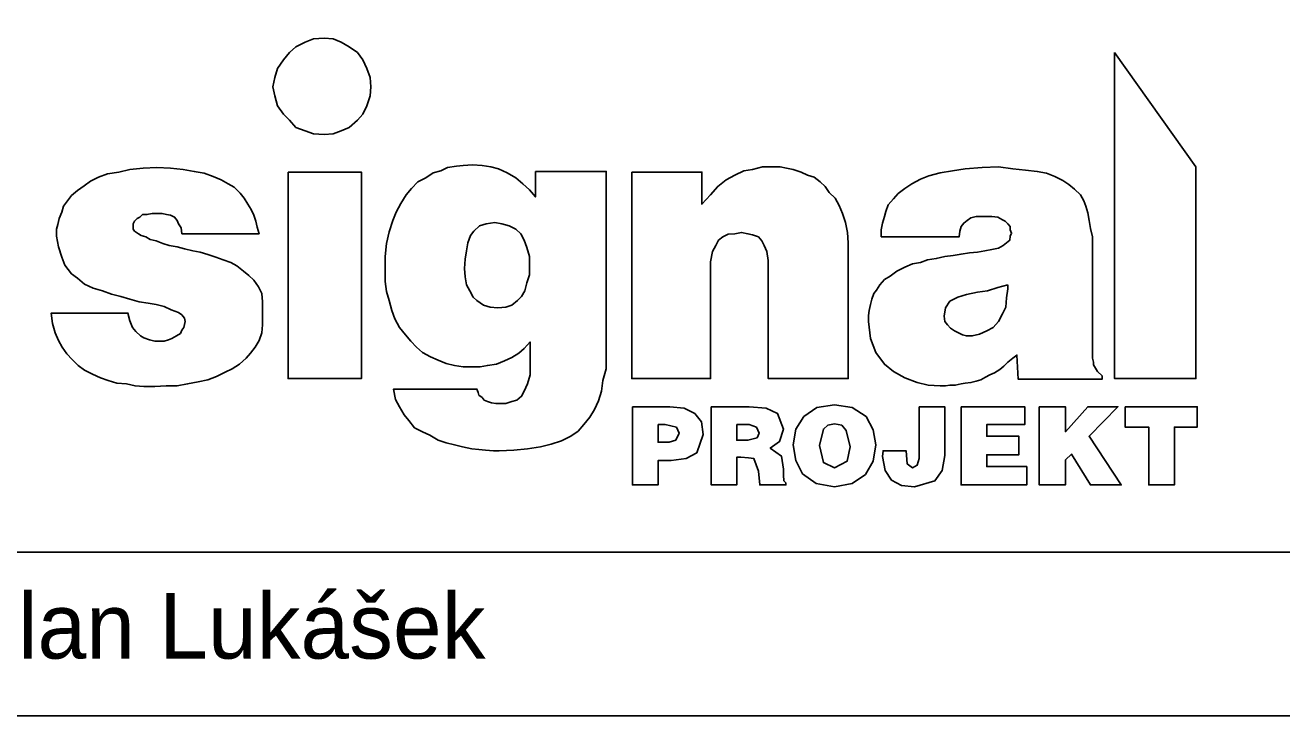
# Model space of a CAD drawing. Extents: x -1210 to -790, y -790 to -493.
# Drawn here: x -866.75 to -828.37, y -690 to -668.9 of the extents above; entities that cross this region are included whole.
import ezdxf

# ---------------------------------------------------------------- set-up
doc = ezdxf.new("R2010")
doc.units = 0
for name, color, linetype in [('Info o rozpiskách', 7, 'Continuous'), ('popis', 7, 'Continuous'), ('Rozpiska_pole_6', 7, 'Continuous')]:
    doc.layers.add(name, color=color, linetype=linetype)

msp = doc.modelspace()

# ---------------------------------------------------------------- linework, layer by layer
at = {"layer": 'Info o rozpiskách'}
for points in [[(-857.618, -669.303), (-857.338, -669.322), (-857.097, -669.422), (-856.857, -669.563), (-856.597, -669.743), (-856.437, -669.963), (-856.316, -670.224), (-856.216, -670.504), (-856.196, -670.785), (-856.216, -671.065), (-856.316, -671.366), (-856.437, -671.626), (-856.597, -671.806), (-856.857, -672.027), (-857.097, -672.127), (-857.338, -672.227), (-857.618, -672.247), (-857.939, -672.227), (-858.199, -672.127), (-858.48, -672.027), (-858.68, -671.806), (-858.86, -671.626), (-859.041, -671.366), (-859.121, -671.065), (-859.181, -670.785), (-859.121, -670.504), (-859.041, -670.224), (-858.86, -669.963), (-858.68, -669.743), (-858.48, -669.563), (-858.199, -669.422), (-857.939, -669.322), (-857.618, -669.303)], [(-848.203, -680.56), (-847.061, -680.56), (-846.621, -680.601), (-846.3, -680.761), (-846.1, -681.022), (-846.04, -681.402), (-846.24, -681.963), (-846.561, -682.144), (-847.021, -682.203), (-847.422, -682.203), (-847.422, -682.945), (-848.203, -682.945), (-848.203, -680.56)], [(-845.799, -680.56), (-844.637, -680.56), (-844.117, -680.601), (-843.776, -680.761), (-843.596, -681.242), (-843.716, -681.622), (-843.996, -681.823), (-843.656, -682.063), (-843.596, -682.464), (-843.596, -682.644), (-843.576, -682.825), (-843.515, -682.885), (-843.515, -682.945), (-844.317, -682.945), (-844.357, -682.524), (-844.497, -682.144), (-844.658, -682.123), (-844.898, -682.103), (-845.018, -682.103), (-845.018, -682.945), (-845.799, -682.945), (-845.799, -680.56)], [(-842.033, -680.501), (-841.492, -680.581), (-841.071, -680.861), (-840.851, -681.262), (-840.771, -681.722), (-840.851, -682.223), (-841.092, -682.624), (-841.492, -682.904), (-842.033, -683.004), (-842.594, -682.904), (-843.015, -682.604), (-843.215, -682.203), (-843.295, -681.722), (-843.215, -681.242), (-842.975, -680.861), (-842.574, -680.581), (-842.033, -680.501)], [(-839.45, -680.56), (-838.668, -680.56), (-838.668, -682.043), (-838.749, -682.504), (-838.969, -682.825), (-839.59, -683.004), (-839.991, -682.964), (-840.291, -682.804), (-840.491, -682.504), (-840.572, -682.083), (-840.552, -681.903), (-839.85, -681.903), (-839.81, -682.304), (-839.65, -682.423), (-839.51, -682.344), (-839.45, -682.144), (-839.45, -680.56)], [(-838.168, -680.56), (-836.224, -680.56), (-836.224, -681.101), (-837.387, -681.101), (-837.387, -681.462), (-836.405, -681.462), (-836.405, -682.023), (-837.387, -682.023), (-837.387, -682.384), (-836.165, -682.384), (-836.165, -682.945), (-838.168, -682.945), (-838.168, -680.56)], [(-835.784, -680.56), (-834.983, -680.56), (-834.983, -681.322), (-834.302, -680.56), (-833.38, -680.56), (-834.261, -681.462), (-833.28, -682.945), (-834.221, -682.945), (-834.802, -682.003), (-834.983, -682.183), (-834.983, -682.945), (-835.784, -682.945), (-835.784, -680.56)], [(-833.159, -680.56), (-830.956, -680.56), (-830.956, -681.182), (-831.657, -681.182), (-831.657, -682.945), (-832.439, -682.945), (-832.439, -681.182), (-833.159, -681.182), (-833.159, -680.56)], [(-847.422, -681.101), (-847.422, -681.642), (-847.081, -681.642), (-846.881, -681.582), (-846.781, -681.362), (-846.861, -681.182), (-847.202, -681.101), (-847.422, -681.101)], [(-845.018, -681.101), (-845.018, -681.582), (-844.677, -681.582), (-844.397, -681.503), (-844.337, -681.362), (-844.417, -681.182), (-844.637, -681.101), (-845.018, -681.101)], [(-842.033, -681.082), (-842.233, -681.122), (-842.374, -681.242), (-842.494, -681.742), (-842.374, -682.263), (-842.033, -682.423), (-841.652, -682.223), (-841.552, -681.782), (-841.673, -681.282), (-841.812, -681.122), (-842.033, -681.082)]]:
    msp.add_lwpolyline(points, dxfattribs=at)
at = {"layer": 'popis'}
for points in [[(-833.48, -669.743), (-833.48, -679.7), (-830.996, -679.7), (-830.996, -673.229), (-833.48, -669.743)], [(-861.966, -675.272), (-859.602, -675.272), (-859.662, -675.072), (-859.702, -674.891), (-859.762, -674.712), (-859.842, -674.531), (-859.943, -674.371), (-860.062, -674.19), (-860.182, -674.03), (-860.363, -673.85), (-860.543, -673.75), (-860.763, -673.629), (-861.004, -673.529), (-861.284, -673.429), (-861.585, -673.369), (-861.925, -673.309), (-862.306, -673.269), (-862.726, -673.249), (-863.147, -673.269), (-863.548, -673.309), (-863.888, -673.389), (-864.229, -673.449), (-864.51, -673.549), (-864.75, -673.669), (-864.95, -673.81), (-865.151, -673.95), (-865.331, -674.11), (-865.451, -674.271), (-865.572, -674.431), (-865.631, -674.611), (-865.712, -674.812), (-865.751, -674.991), (-865.792, -675.132), (-865.792, -675.353), (-865.732, -675.673), (-865.631, -675.993), (-865.531, -676.234), (-865.331, -676.494), (-865.151, -676.634), (-864.931, -676.815), (-864.67, -676.935), (-864.39, -677.015), (-864.109, -677.115), (-863.828, -677.195), (-863.548, -677.275), (-863.268, -677.356), (-862.987, -677.395), (-862.747, -677.435), (-862.506, -677.496), (-862.286, -677.596), (-862.066, -677.676), (-861.966, -677.756), (-861.885, -677.856), (-861.865, -677.956), (-861.906, -678.137), (-861.966, -678.217), (-862.006, -678.317), (-862.126, -678.397), (-862.266, -678.478), (-862.366, -678.517), (-862.506, -678.557), (-862.647, -678.557), (-862.787, -678.557), (-862.947, -678.517), (-863.128, -678.457), (-863.228, -678.397), (-863.368, -678.257), (-863.468, -678.137), (-863.548, -677.937), (-863.608, -677.696), (-865.952, -677.696), (-865.912, -678.016), (-865.832, -678.297), (-865.732, -678.538), (-865.612, -678.738), (-865.471, -678.938), (-865.311, -679.119), (-865.131, -679.298), (-864.931, -679.439), (-864.69, -679.559), (-864.45, -679.679), (-864.209, -679.759), (-863.949, -679.839), (-863.648, -679.86), (-863.388, -679.92), (-863.128, -679.94), (-862.787, -679.94), (-862.446, -679.92), (-862.106, -679.92), (-861.785, -679.86), (-861.465, -679.8), (-861.165, -679.739), (-860.904, -679.639), (-860.643, -679.499), (-860.423, -679.398), (-860.203, -679.259), (-860.002, -679.078), (-859.862, -678.918), (-859.722, -678.738), (-859.602, -678.538), (-859.522, -678.297), (-859.501, -678.057), (-859.501, -677.816), (-859.501, -677.756), (-859.501, -677.696), (-859.501, -677.636), (-859.501, -677.576), (-859.501, -677.496), (-859.501, -677.435), (-859.501, -677.395), (-859.501, -677.356), (-859.522, -677.095), (-859.622, -676.895), (-859.762, -676.694), (-859.922, -676.554), (-860.082, -676.414), (-860.282, -676.254), (-860.463, -676.153), (-860.703, -676.073), (-860.924, -675.993), (-861.165, -675.913), (-861.404, -675.833), (-861.625, -675.793), (-861.885, -675.733), (-862.106, -675.673), (-862.346, -675.632), (-862.547, -675.572), (-862.747, -675.493), (-862.927, -675.453), (-863.067, -675.372), (-863.207, -675.332), (-863.288, -675.272), (-863.407, -675.192), (-863.448, -675.132), (-863.448, -675.052), (-863.448, -674.972), (-863.407, -674.891), (-863.328, -674.812), (-863.247, -674.771), (-863.168, -674.691), (-863.027, -674.691), (-862.867, -674.651), (-862.726, -674.651), (-862.566, -674.651), (-862.426, -674.691), (-862.306, -674.712), (-862.186, -674.771), (-862.106, -674.872), (-862.066, -674.972), (-861.985, -675.092), (-861.966, -675.272)], [(-858.72, -673.389), (-858.72, -679.7), (-856.477, -679.7), (-856.477, -673.389), (-858.72, -673.389)], [(-851.168, -673.369), (-851.168, -674.15), (-851.349, -673.93), (-851.549, -673.75), (-851.769, -673.569), (-852.03, -673.409), (-852.29, -673.289), (-852.53, -673.229), (-852.791, -673.188), (-853.091, -673.169), (-853.372, -673.188), (-853.572, -673.209), (-853.852, -673.249), (-854.053, -673.349), (-854.293, -673.409), (-854.513, -673.569), (-854.754, -673.69), (-854.954, -673.89), (-855.115, -674.09), (-855.275, -674.35), (-855.415, -674.611), (-855.515, -674.872), (-855.635, -675.212), (-855.715, -675.572), (-855.756, -675.973), (-855.756, -676.394), (-855.756, -676.735), (-855.715, -677.035), (-855.635, -677.316), (-855.555, -677.616), (-855.455, -677.876), (-855.315, -678.137), (-855.134, -678.357), (-854.974, -678.557), (-854.794, -678.738), (-854.613, -678.898), (-854.374, -679.038), (-854.133, -679.138), (-853.893, -679.238), (-853.632, -679.298), (-853.372, -679.339), (-853.091, -679.339), (-852.85, -679.339), (-852.63, -679.298), (-852.35, -679.259), (-852.109, -679.159), (-851.889, -679.059), (-851.669, -678.918), (-851.509, -678.778), (-851.328, -678.578), (-851.328, -679.159), (-851.328, -679.579), (-851.409, -679.86), (-851.509, -680.08), (-851.589, -680.24), (-851.729, -680.36), (-851.889, -680.4), (-852.069, -680.46), (-852.269, -680.46), (-852.37, -680.46), (-852.51, -680.441), (-852.63, -680.4), (-852.731, -680.36), (-852.791, -680.281), (-852.891, -680.2), (-852.911, -680.12), (-852.951, -680.02), (-855.495, -680.02), (-855.435, -680.341), (-855.315, -680.56), (-855.175, -680.801), (-855.034, -680.981), (-854.854, -681.201), (-854.613, -681.322), (-854.393, -681.422), (-854.133, -681.582), (-853.893, -681.663), (-853.632, -681.722), (-853.391, -681.782), (-853.111, -681.842), (-852.891, -681.863), (-852.69, -681.883), (-852.45, -681.903), (-852.269, -681.903), (-851.829, -681.883), (-851.409, -681.842), (-851.008, -681.782), (-850.687, -681.703), (-850.367, -681.603), (-850.086, -681.462), (-849.866, -681.302), (-849.686, -681.101), (-849.505, -680.881), (-849.365, -680.641), (-849.245, -680.381), (-849.145, -680.08), (-849.105, -679.759), (-849.005, -679.398), (-849.005, -679.018), (-849.005, -678.578), (-849.005, -673.369), (-851.168, -673.369)], [(-848.224, -673.389), (-848.224, -679.7), (-845.819, -679.7), (-845.819, -676.474), (-845.819, -676.134), (-845.759, -675.813), (-845.659, -675.632), (-845.579, -675.472), (-845.439, -675.372), (-845.278, -675.292), (-845.078, -675.272), (-844.878, -675.232), (-844.677, -675.272), (-844.537, -675.312), (-844.357, -675.372), (-844.256, -675.493), (-844.177, -675.632), (-844.096, -675.813), (-844.056, -676.094), (-844.056, -676.374), (-844.056, -679.7), (-841.612, -679.7), (-841.612, -675.893), (-841.612, -675.553), (-841.633, -675.232), (-841.693, -674.932), (-841.793, -674.651), (-841.893, -674.41), (-842.014, -674.19), (-842.193, -674.01), (-842.314, -673.829), (-842.474, -673.69), (-842.654, -673.549), (-842.855, -673.49), (-843.055, -673.389), (-843.295, -673.309), (-843.496, -673.269), (-843.696, -673.229), (-843.936, -673.229), (-844.237, -673.229), (-844.537, -673.309), (-844.798, -673.349), (-845.078, -673.49), (-845.339, -673.629), (-845.599, -673.829), (-845.819, -674.09), (-846.08, -674.371), (-846.08, -673.389), (-848.224, -673.389)], [(-840.612, -675.372), (-838.228, -675.372), (-838.208, -675.192), (-838.168, -675.052), (-838.087, -674.951), (-837.987, -674.872), (-837.867, -674.791), (-837.707, -674.751), (-837.567, -674.751), (-837.406, -674.751), (-837.227, -674.751), (-837.046, -674.771), (-836.906, -674.851), (-836.825, -674.891), (-836.746, -674.972), (-836.665, -675.052), (-836.665, -675.152), (-836.625, -675.252), (-836.665, -675.353), (-836.685, -675.472), (-836.786, -675.553), (-836.886, -675.632), (-837.025, -675.713), (-837.227, -675.753), (-837.447, -675.793), (-837.667, -675.833), (-837.908, -675.853), (-838.168, -675.893), (-838.408, -675.934), (-838.668, -675.973), (-838.929, -676.034), (-839.19, -676.073), (-839.41, -676.153), (-839.65, -676.194), (-839.89, -676.294), (-840.131, -676.414), (-840.331, -676.574), (-840.512, -676.675), (-840.652, -676.835), (-840.751, -676.995), (-840.831, -677.095), (-840.892, -677.275), (-840.931, -677.435), (-840.971, -677.616), (-840.992, -677.776), (-840.992, -677.956), (-840.931, -678.478), (-840.771, -678.898), (-840.512, -679.259), (-840.231, -679.479), (-839.89, -679.679), (-839.51, -679.819), (-839.169, -679.9), (-838.809, -679.92), (-838.649, -679.92), (-838.508, -679.9), (-838.348, -679.9), (-838.168, -679.86), (-838.047, -679.839), (-837.867, -679.819), (-837.707, -679.779), (-837.567, -679.739), (-837.427, -679.659), (-837.286, -679.579), (-837.146, -679.519), (-836.986, -679.419), (-836.865, -679.319), (-836.746, -679.198), (-836.585, -679.078), (-836.465, -678.978), (-836.425, -679.719), (-833.861, -679.719), (-833.861, -679.619), (-834.001, -679.479), (-834.061, -679.379), (-834.121, -679.279), (-834.121, -679.198), (-834.161, -679.078), (-834.161, -678.998), (-834.161, -678.878), (-834.161, -678.718), (-834.161, -675.632), (-834.161, -675.372), (-834.221, -675.112), (-834.261, -674.872), (-834.302, -674.631), (-834.362, -674.431), (-834.422, -674.271), (-834.522, -674.09), (-834.702, -673.91), (-834.883, -673.769), (-835.062, -673.65), (-835.303, -673.529), (-835.564, -673.429), (-835.844, -673.369), (-836.205, -673.329), (-836.585, -673.289), (-837.025, -673.229), (-837.527, -673.249), (-838.047, -673.289), (-838.428, -673.349), (-838.809, -673.409), (-839.149, -673.509), (-839.41, -673.609), (-839.67, -673.75), (-839.89, -673.89), (-840.091, -674.05), (-840.231, -674.21), (-840.391, -674.391), (-840.471, -674.591), (-840.512, -674.751), (-840.572, -674.951), (-840.612, -675.152), (-840.612, -675.372)], [(-852.41, -674.932), (-852.19, -674.972), (-851.969, -675.032), (-851.769, -675.132), (-851.609, -675.272), (-851.509, -675.472), (-851.428, -675.693), (-851.349, -675.973), (-851.349, -676.274), (-851.349, -676.534), (-851.428, -676.775), (-851.488, -677.015), (-851.589, -677.195), (-851.709, -677.316), (-851.889, -677.456), (-852.069, -677.516), (-852.31, -677.535), (-852.55, -677.516), (-852.75, -677.456), (-852.951, -677.316), (-853.071, -677.215), (-853.171, -677.015), (-853.271, -676.835), (-853.312, -676.594), (-853.331, -676.334), (-853.312, -676.053), (-853.271, -675.793), (-853.231, -675.553), (-853.152, -675.332), (-853.051, -675.192), (-852.871, -675.032), (-852.671, -674.972), (-852.41, -674.932)], [(-836.746, -676.835), (-836.746, -676.854), (-836.746, -676.915), (-836.746, -676.954), (-836.786, -677.235), (-836.806, -677.516), (-836.906, -677.716), (-837.025, -677.956), (-837.186, -678.137), (-837.387, -678.237), (-837.607, -678.337), (-837.827, -678.397), (-838.008, -678.397), (-838.128, -678.357), (-838.247, -678.297), (-838.368, -678.237), (-838.488, -678.157), (-838.588, -678.057), (-838.668, -677.956), (-838.688, -677.796), (-838.649, -677.535), (-838.508, -677.335), (-838.268, -677.215), (-838.008, -677.135), (-837.667, -677.055), (-837.366, -677.015), (-837.046, -676.915), (-836.746, -676.835)]]:
    msp.add_lwpolyline(points, dxfattribs=at)
at = {"layer": 'Rozpiska_pole_6'}
msp.add_line((-980, -685), (-810, -685), dxfattribs=at)
msp.add_lwpolyline([(-980, -650), (-810, -650), (-810, -690), (-980, -690)], close=True, dxfattribs=at)

# ---------------------------------------------------------------- texts
msp.add_text('Ing. Milan Lukášek', height=2, dxfattribs=at).set_placement((-874.991, -688.25))

doc.saveas('drawing.dxf')
